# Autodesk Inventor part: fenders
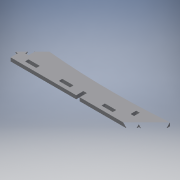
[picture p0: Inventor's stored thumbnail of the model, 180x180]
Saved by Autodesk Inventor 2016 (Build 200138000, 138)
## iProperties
Created: 2017-06
Part Number: fenders
Material: Generic
Document SubType Name: Modeling
Designer: laboratorioesan
Density: 1 g/cm^3
Appearance: Default
Author: laboratorioesan
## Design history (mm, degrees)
sketch "Sketch1"
  geometry: L1 (1057.5, 18.5)-(1117.5, 18.5) reference; L2 (1057.5, 18.5)-(1057.5, 0) reference; L3 (1117.5, 0)-(1057.5, 0) reference; L4 (1117.5, 18.5)-(1117.5, 0) reference; L5 (877.5, 18.5)-(937.5, 18.5) reference; L6 (877.5, 18.5)-(877.5, 0) reference; L7 (937.5, 0)-(877.5, 0) reference; L8 (937.5, 18.5)-(937.5, 0) reference; L9 (649.863, 18.5)-(709.863, 18.5) reference; L10 (649.863, 18.5)-(649.863, 0) reference; L11 (709.863, 0)-(649.863, 0) reference; L12 (709.863, 18.5)-(709.863, 0) reference; L13 (469.863, 18.5)-(529.863, 18.5) reference; L14 (469.863, 18.5)-(469.863, 0) reference; L15 (529.863, 0)-(469.863, 0) reference; L16 (529.863, 18.5)-(529.863, 0) reference; L17 (1117.5, 18.5)-(1550, 18.5) reference; L18 (937.5, 18.5)-(1057.5, 18.5) reference; L19 (709.863, 18.5)-(877.5, 18.5) reference; L20 (529.863, 18.5)-(649.863, 18.5) reference; L21 (0, 18.5)-(469.863, 18.5) reference; L22 (0, 0)-(469.863, 0) reference; L23 (529.863, 0)-(649.863, 0) reference; L24 (709.863, 0)-(877.5, 0) reference; L25 (1137.5, 18.5)-(1137.5, 0) reference; L26 (325.59, -20)-(325.59, 130); L27 (1137.5, 105)-(1137.5, -20); L28 (1012.477, 38.5)-(993.977, 38.5); L29 (993.977, 38.5)-(993.977, 68.5); L30 (993.977, 68.5)-(1012.477, 68.5); L31 (1012.477, 68.5)-(1012.477, 38.5); L32 (451.09, 38.5)-(432.59, 38.5); L33 (432.59, 38.5)-(432.59, 68.5); L34 (432.59, 68.5)-(451.09, 68.5); L35 (451.09, 68.5)-(451.09, 38.5); L36 (394, -17.186)-(394, 18.5) reference; L37 (412.5, -17.186)-(412.5, 18.5) reference; L38 (412.5, -20)-(412.5, 18.5); L39 (412.5, 18.5)-(394, 18.5); L40 (394, 18.5)-(394, -20); L41 (394, -20)-(325.59, -20); L42 (781, 18.5)-(781, -17.186) reference; L43 (762.5, 18.5)-(762.5, -17.186) reference; L44 (781, -20)-(781, 18.5); L45 (781, 18.5)-(762.5, 18.5); L46 (762.5, 18.5)-(762.5, -20); L47 (1137.5, -20)-(781, -20); L48 (762.5, -20)-(412.5, -20); A1 r 3569.02 centre (840.675, 3661.655) between (325.59, 130) and (1137.5, 105)
  constraints: 38 end point, 11 perpendicular, 5 horizontal, 5 parallel, 2 horizontal alignment, 2 point on circle, 1 centre point, 1 collinear, 1 point on line
  dimensions: "d1" = 125 distance of L27.start L27.end; "d2" = 20 horizontal distance of L27.end L3.start; "d3" = 150 distance of L26.end L26.start; "d4" = 18.5 distance of L29.end L30.end; "d5" = 30 distance of L28.end L29.end; "d6" = 20 distance from line of L18 L28.end; "d7" = 18.5 distance of L33.end L34.end; "d8" = 20 distance between parallel lines of L21 L32; "d9" = 107 distance from line of L26 L33.end; "d12" = 30 distance of L32.end L33.end
extrude "Extrusion1" new body sketch "Sketch1" distance "d10" = 18.5; taper "d11" = 0 deg
sketch "Sketch2"
  geometry: L1 (529.863, 0)-(469.863, 0) reference; L2 (469.863, 0)-(469.863, 18.5) reference; L3 (469.863, 18.5)-(529.863, 18.5) reference; L4 (529.863, 18.5)-(529.863, 0) reference; L5 (762.5, 18.5)-(781, 18.5) reference; L6 (781, 18.5)-(781, -20) reference; L7 (781, -20)-(1137.5, -20) reference; L8 (1137.5, -20)-(1137.5, 105) reference; L9 (325.59, 130)-(325.59, -20) reference; L10 (325.59, -20)-(394, -20) reference; L11 (394, -20)-(394, 18.5) reference; L12 (394, 18.5)-(412.5, 18.5) reference; L13 (412.5, 18.5)-(412.5, -20) reference; L14 (412.5, -20)-(762.5, -20) reference; L15 (762.5, -20)-(762.5, 18.5) reference; L16 (937.5, 18.5)-(937.5, 0) reference; L17 (937.5, 0)-(877.5, 0) reference; L18 (877.5, 0)-(877.5, 18.5) reference; L19 (877.5, 18.5)-(937.5, 18.5) reference; L20 (1057.5, 18.5)-(1117.5, 18.5) reference; L21 (1117.5, 18.5)-(1117.5, 0) reference; L22 (1117.5, 0)-(1057.5, 0) reference; L23 (1057.5, 0)-(1057.5, 18.5) reference; L24 (432.59, 38.5)-(432.59, 68.5) reference; L25 (432.59, 68.5)-(451.09, 68.5) reference; L26 (451.09, 68.5)-(451.09, 38.5) reference; L27 (451.09, 38.5)-(432.59, 38.5) reference; L28 (993.977, 38.5)-(993.977, 68.5) reference; L29 (993.977, 68.5)-(1012.477, 68.5) reference; L30 (1012.477, 68.5)-(1012.477, 38.5) reference; L31 (1012.477, 38.5)-(993.977, 38.5) reference; L32 (649.863, 0)-(649.863, 18.5) reference; L33 (649.863, 18.5)-(709.863, 18.5) reference; L34 (709.863, 18.5)-(709.863, 0) reference; L35 (709.863, 0)-(649.863, 0) reference; L36 (394, 18.5)-(412.5, 18.5) reference; L37 (394, 18.5)-(394, 120.697); A1 r 3569.02 centre (840.675, 3661.655) between (325.59, 130) and (1137.5, 105) reference; 1 further point
  constraints: 2 end point, 1 point on circle, 1 vertical
extrude "Extrusion2" cut sketch "Sketch2" distance "d13" = 18.5; taper "d14" = 0 deg
body "Solid1"
node "Reference1"
node "Reference2"
node "Reference3"
node "Reference4"
node "Reference5"
node "Reference6"
node "Reference7"
node "Reference8"
node "Reference9"
node "Reference10"
node "Reference11"
node "Reference12"
node "Reference13"
node "Reference14"
node "Reference15"
node "Reference16"
node "Reference17"
node "Projected Loop1"
